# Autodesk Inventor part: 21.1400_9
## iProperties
Created: 2006-12
Part Number: 21.1400_9
Document SubType Name: Modeling
Designer: Andy Moles
Material: Alloy Steel
Density: 7.85 g/cm^3
Description: MITER CON SECT 1 MODIFIED
Mass: 20.5329 g
Surface Area: 16.2437 cm^2
Volume: 2.61565 cm^3
Author: Andy Moles
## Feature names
1. Extrusion1
2. Revolution1
3. Extrusion2
4. Extrusion3
5. Chamfer1
6. Hole1
7. Chamfer2
8. Hole2
